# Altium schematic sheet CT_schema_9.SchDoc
size 274 x 160 mm
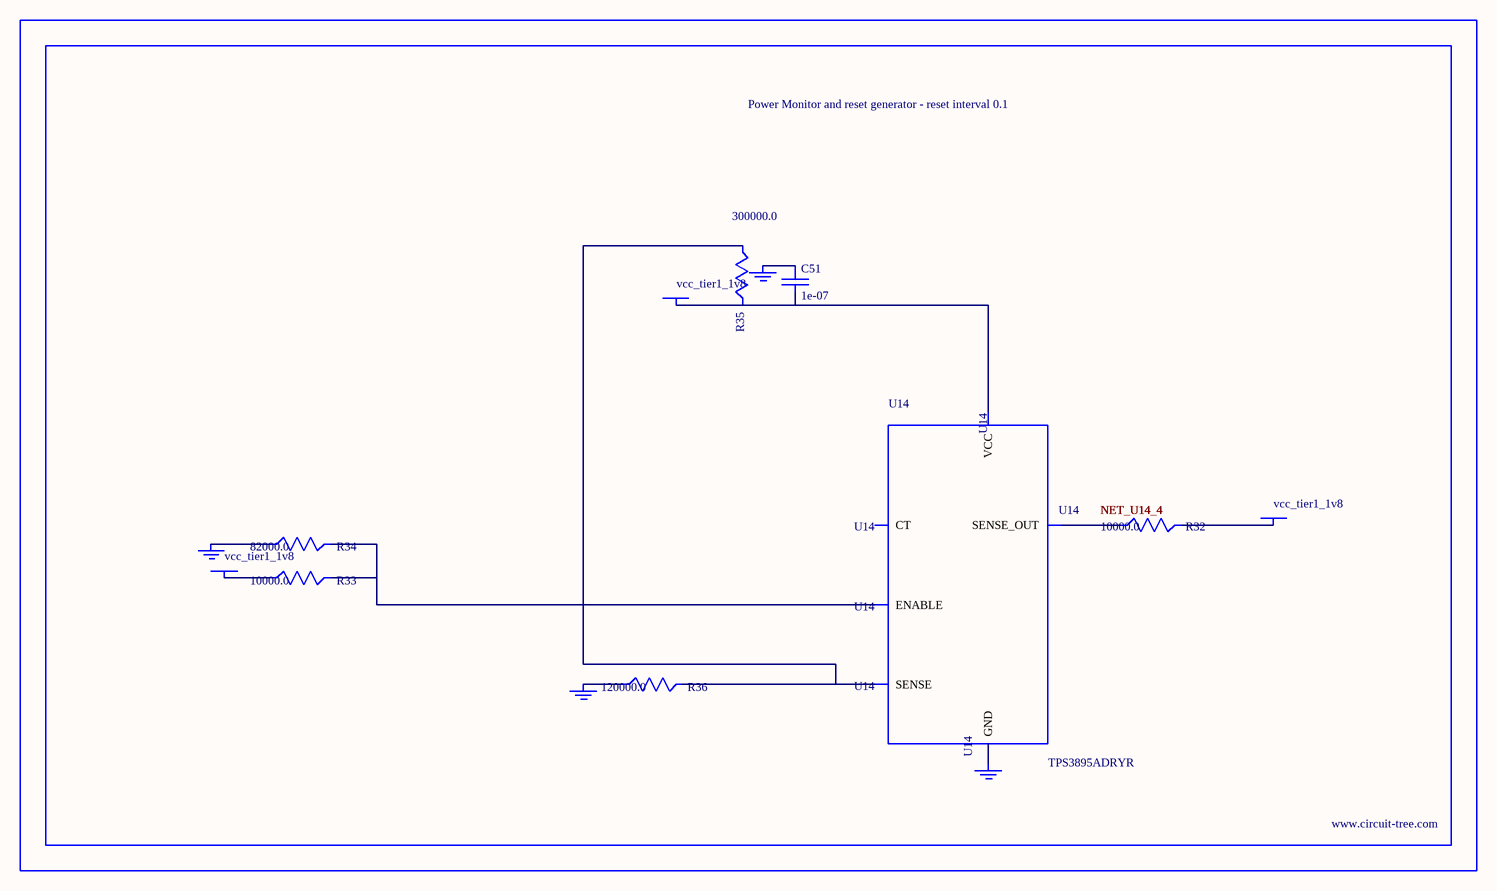
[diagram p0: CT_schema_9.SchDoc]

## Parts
BORDER8  (no value)
C51  1e-07  [C0402]
GND_INSTANCE_8_0  (no value)
GND_INSTANCE_8_1  (no value)
GND_INSTANCE_8_2  (no value)
GND_INSTANCE_8_3  (no value)
POWER_INSTANCE_8_0  vcc_tier1_1v8
POWER_INSTANCE_8_1  vcc_tier1_1v8
POWER_INSTANCE_8_2  vcc_tier1_1v8
R32  10000.0  [R0603]
R33  10000.0  [R0603]
R34  82000.0  [R0603]
R35  300000.0  [R0603]
R36  120000.0  [R0603]
U14  TPS3895ADRYR  [SON-6]

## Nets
NetC51_1: C51.1 GND_INSTANCE_8_2.0(GND)
NetC51_2: C51.2 POWER_INSTANCE_8_2.0(PWR) R35.2 U14.6(VCC)
NetGND_INSTANCE_8_0_0: GND_INSTANCE_8_0.0(GND) R34.1
NetGND_INSTANCE_8_1_0: GND_INSTANCE_8_1.0(GND) R36.1
NetGND_INSTANCE_8_3_0: GND_INSTANCE_8_3.0(GND) U14.2(GND)
NetPOWER_INSTANCE_8_0_0: POWER_INSTANCE_8_0.0(PWR) R33.1
NetPOWER_INSTANCE_8_1_0: POWER_INSTANCE_8_1.0(PWR) R32.2
NetR32_1: R32.1 U14.4(SENSE_OUT)
NetR33_2: R33.2 R34.2 U14.1(ENABLE)
NetR35_1: R35.1 R36.2 U14.3(SENSE)

Not connected (* = marked no-connect by the designer): U14 5(CT)

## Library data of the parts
BORDER8 = BORDER_PAGE8
C51 = C0402C104K3RACTU
GND_INSTANCE_8_0-GND_INSTANCE_8_3 = GND
POWER_INSTANCE_8_0-POWER_INSTANCE_8_2 = PWR
R32 R33 = RC0603JR-0710KL
R34 = RC0603JR-0782KL
R35 = RC0603JR-07300KL
R36 = RC0603JR-07120KL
